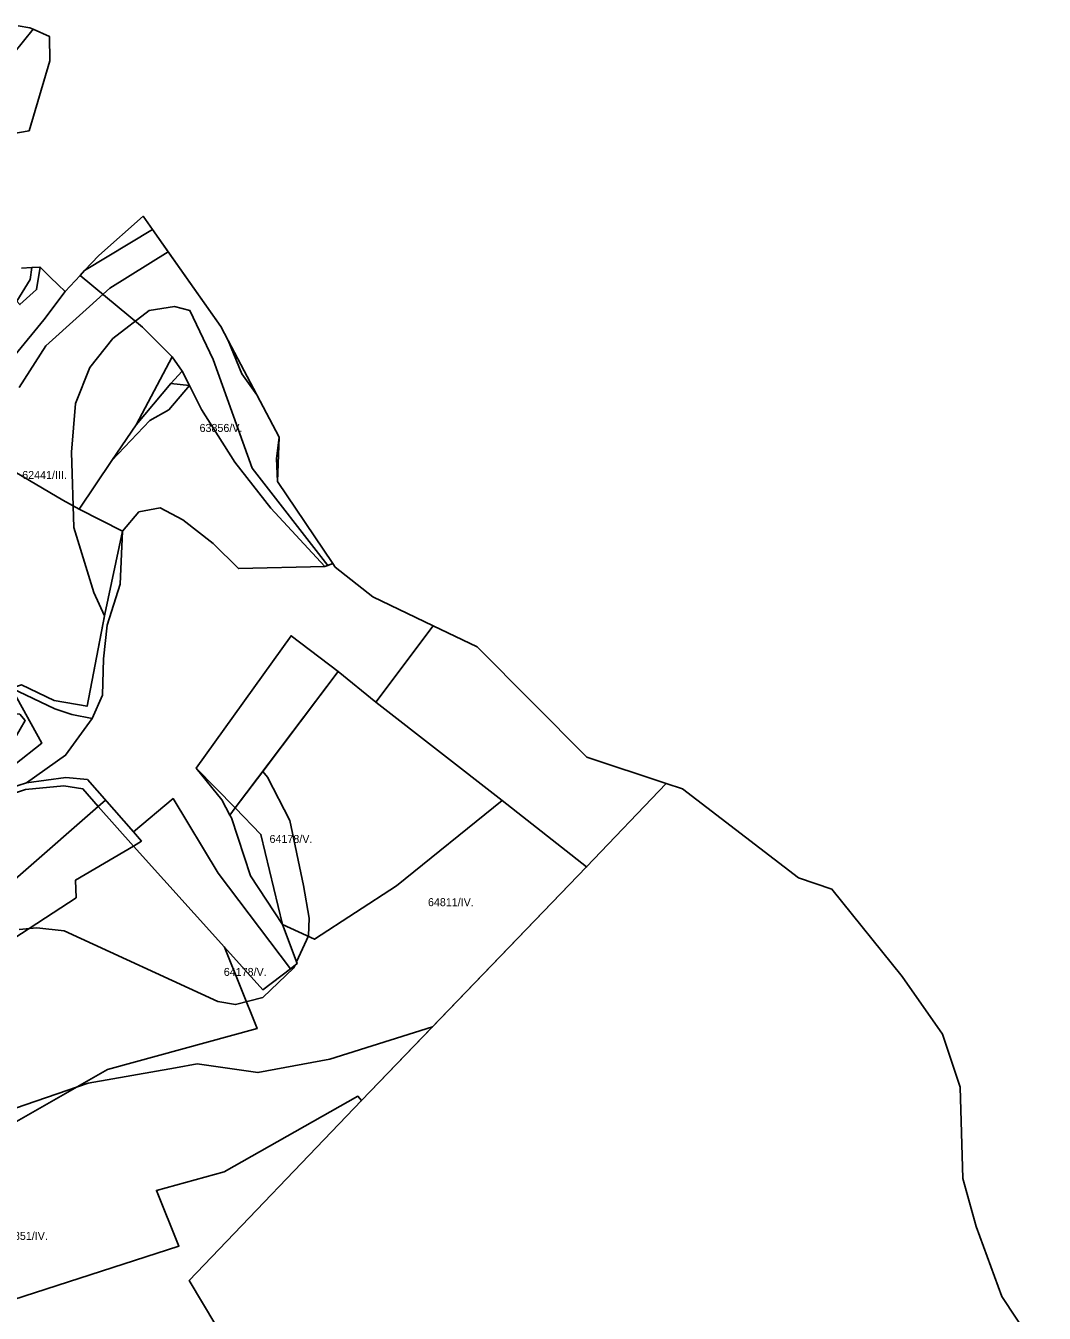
# Model space of a CAD drawing. Extents: x -521261 to -517465, y -1182764 to -1179456.
# Drawn here: x -518235 to -517599, y -1182247 to -1181443 of the extents above; entities that cross this region are included whole.
import ezdxf

# ---------------------------------------------------------------- set-up
doc = ezdxf.new("R2010")
doc.units = 0
for name, color, linetype in [('95560013', 7, 'Continuous'), ('95610013', 7, 'Continuous'), ('95620013', 7, 'Continuous'), ('95630013', 7, 'Continuous'), ('95640013', 7, 'Continuous'), ('95660013', 7, 'Continuous')]:
    doc.layers.add(name, color=color, linetype=linetype)

msp = doc.modelspace()

# ---------------------------------------------------------------- linework, layer by layer
at = {"layer": '95560013'}
for points in [[(-518039.97, -1181846.02), (-518016.25, -1181865.06), (-517937.47, -1181926.51), (-518003.38, -1181979.84), (-518054.75, -1182013.18), (-518074.66, -1182003.92), (-518088.11, -1181947.65), (-518104.15, -1181931.16)], [(-517937.47, -1181926.51), (-517884.7, -1181968.01), (-518025.29, -1182113.9), (-518027.56, -1182111.28), (-518111.08, -1182158.35), (-518153.43, -1182170.1), (-518139.38, -1182204.87), (-518263.83, -1182245.02), (-518424.06, -1182333.99), (-518433.13, -1182315.06), (-518318.58, -1182239.54), (-518350.96, -1182190.35), (-518347.31, -1182180.7), (-518335.12, -1182204.11), (-518240.87, -1182127.03), (-518183.99, -1182094.63), (-518090.51, -1182068.93), (-518110.82, -1182018.11), (-518086.87, -1182044.67), (-518069.54, -1182031.68), (-518065.44, -1182028.22), (-518074.66, -1182003.92), (-518054.75, -1182013.18), (-518003.38, -1181979.84)], [(-518107.48, -1181935.62), (-518104.15, -1181931.16), (-518088.11, -1181947.65), (-518074.66, -1182003.92), (-518094.59, -1181973.57), (-518106.56, -1181937.37)], [(-518167.73, -1181955), (-518110.82, -1182018.11), (-518090.51, -1182068.93), (-518183.99, -1182094.63), (-518240.87, -1182127.03), (-518335.12, -1182204.11), (-518347.31, -1182180.7), (-518342.86, -1182166.04), (-518356.01, -1182102.22), (-518326.89, -1182075.42), (-518296.03, -1182047.39), (-518203.6, -1181987.3), (-518203.86, -1181976.19)]]:
    msp.add_lwpolyline(points, close=True, dxfattribs=at)
at = {"layer": '95610013'}
for points in [[(-518230.37, -1181444.73), (-518220.1, -1181449.28), (-518219.98, -1181464.38), (-518232.93, -1181508.15), (-518243.76, -1181510.04), (-518252.51, -1181510.92), (-518261.84, -1181503.31), (-518242.44, -1181459.71)], [(-518198.24, -1181595.51), (-518155.8, -1181569.88), (-518113.09, -1181630.49), (-518108.52, -1181639.23), (-518100.06, -1181660.08), (-518090.66, -1181673.2), (-518076.8, -1181699.59), (-518078.28, -1181712.88), (-518077.8, -1181727.26), (-518043.21, -1181778.53), (-518048.19, -1181780.36), (-518081.84, -1181743.97), (-518104.4, -1181715.24), (-518125.2, -1181682.29), (-518132.78, -1181667.2), (-518137.2, -1181658.38), (-518143.65, -1181649.33), (-518162.04, -1181630.84), (-518201.08, -1181598.66)], [(-518231.23, -1181593.65), (-518226.03, -1181593.35), (-518228.23, -1181607.32), (-518238.63, -1181616.76), (-518240.53, -1181614.63), (-518232.17, -1181601.16)], [(-518210.43, -1181608.65), (-518201.08, -1181598.66), (-518162.04, -1181630.84), (-518143.65, -1181649.33), (-518166.09, -1181691.8), (-518181.28, -1181714.22), (-518201.57, -1181744.52), (-518211.74, -1181738.87), (-518271.03, -1181704.12), (-518268.81, -1181694.86), (-518257.78, -1181667.72), (-518223.62, -1181626.24)], [(-518108.52, -1181639.23), (-518090.66, -1181673.2), (-518100.06, -1181660.08)], [(-518143.65, -1181649.33), (-518137.2, -1181658.38), (-518144.4, -1181665.99), (-518166.09, -1181691.8)], [(-518137.2, -1181658.38), (-518132.78, -1181667.2), (-518144.4, -1181665.99)], [(-518132.78, -1181667.2), (-518125.2, -1181682.29), (-518104.4, -1181715.24), (-518081.84, -1181743.97), (-518048.19, -1181780.36), (-518102.12, -1181781.59), (-518117.96, -1181765.95), (-518136.81, -1181751.12), (-518151.04, -1181743.73), (-518164.27, -1181746.2), (-518174.5, -1181758.25), (-518201.57, -1181744.52), (-518181.28, -1181714.22), (-518157.59, -1181689.15), (-518145.72, -1181682.4)], [(-518132.78, -1181667.2), (-518145.72, -1181682.4), (-518157.59, -1181689.15), (-518181.28, -1181714.22), (-518166.09, -1181691.8), (-518144.4, -1181665.99)], [(-518273.51, -1181713.67), (-518271.03, -1181704.12), (-518211.74, -1181738.87), (-518201.57, -1181744.52), (-518174.5, -1181758.25), (-518185.6, -1181810.01), (-518196.73, -1181867.61), (-518217.29, -1181863.99), (-518237.7, -1181854.2), (-518243.96, -1181856.31), (-518273.09, -1181840.42), (-518283.47, -1181831.75), (-518289.97, -1181826.31), (-518302.96, -1181825.14), (-518296.94, -1181818.88), (-518287.7, -1181797.29)], [(-518167.72, -1181946.01), (-518142.94, -1181925.35), (-518114.8, -1181971.88), (-518069.54, -1182031.68), (-518086.87, -1182044.67), (-518110.82, -1182018.11), (-518167.73, -1181955), (-518162.77, -1181951.82)]]:
    msp.add_lwpolyline(points, close=True, dxfattribs=at)
at = {"layer": '95620013'}
for points in [[(-518164.27, -1181746.2), (-518151.04, -1181743.73), (-518136.81, -1181751.12), (-518117.96, -1181765.95), (-518102.12, -1181781.59), (-518048.19, -1181780.36), (-518043.21, -1181778.53), (-518041.71, -1181780.74), (-518018.25, -1181799.32), (-517980.44, -1181817.45), (-518016.25, -1181865.06), (-518039.97, -1181846.02), (-518069.24, -1181823.59), (-518128.46, -1181906.25), (-518112.47, -1181926.13), (-518107.48, -1181935.62), (-518106.56, -1181937.37), (-518094.59, -1181973.57), (-518074.66, -1182003.92), (-518065.44, -1182028.22), (-518069.54, -1182031.68), (-518114.8, -1181971.88), (-518142.94, -1181925.35), (-518167.72, -1181946.01), (-518196.51, -1181913.47), (-518210.04, -1181912.15), (-518234.59, -1181915.51), (-518210.07, -1181898.25), (-518193.46, -1181875.24), (-518187.07, -1181860.77), (-518186.5, -1181837.96), (-518184.18, -1181816.88), (-518176.04, -1181791.27), (-518174.5, -1181758.25)], [(-518174.5, -1181758.25), (-518176.04, -1181791.27), (-518184.18, -1181816.88), (-518186.5, -1181837.96), (-518187.07, -1181860.77), (-518193.46, -1181875.24), (-518206.25, -1181872.88), (-518216.74, -1181869.34), (-518243.96, -1181856.31), (-518237.7, -1181854.2), (-518217.29, -1181863.99), (-518196.73, -1181867.61), (-518185.6, -1181810.01)], [(-517980.44, -1181817.45), (-517953.14, -1181830.53), (-517884.53, -1181899.44), (-517834.98, -1181915.87), (-517884.7, -1181968.01), (-517937.47, -1181926.51), (-518016.25, -1181865.06)], [(-518069.24, -1181823.59), (-518039.97, -1181846.02), (-518104.15, -1181931.16), (-518128.46, -1181906.25)], [(-518243.96, -1181856.31), (-518216.74, -1181869.34), (-518206.25, -1181872.88), (-518193.46, -1181875.24), (-518210.07, -1181898.25), (-518234.59, -1181915.51), (-518260.74, -1181923.8), (-518297.47, -1181944.62), (-518324.52, -1181960.18), (-518292.42, -1181936.84), (-518241.77, -1181903.92), (-518224.92, -1181890.6)], [(-518238.76, -1181872.67), (-518248.46, -1181871.63), (-518262.89, -1181874.89), (-518293.39, -1181886.48), (-518243.96, -1181856.31), (-518224.92, -1181890.6), (-518241.77, -1181903.92), (-518292.42, -1181936.84), (-518241.66, -1181887.31), (-518235.39, -1181876.59)], [(-518112.47, -1181926.13), (-518128.46, -1181906.25), (-518104.15, -1181931.16), (-518107.48, -1181935.62)], [(-518025.29, -1182113.9), (-518132.88, -1182226.29), (-518107.95, -1182268.17), (-518147.76, -1182311.32), (-518306.45, -1182392.72), (-518408.71, -1182440.57), (-518421.69, -1182398.59), (-518461.02, -1182411.93), (-518525.73, -1182463.17), (-518552.56, -1182359.4), (-518559.26, -1182337.41), (-518435.2, -1182310.64), (-518433.13, -1182315.06), (-518424.06, -1182333.99), (-518263.83, -1182245.02), (-518139.38, -1182204.87), (-518153.43, -1182170.1), (-518111.08, -1182158.35), (-518027.56, -1182111.28)]]:
    msp.add_lwpolyline(points, close=True, dxfattribs=at)
for points in [[(-518107.95, -1182268.17), (-518132.88, -1182226.29), (-518025.29, -1182113.9), (-517884.7, -1181968.01), (-517834.98, -1181915.87), (-517824.86, -1181919.18), (-517752.33, -1181974.82), (-517731.51, -1181981.82), (-517687.7, -1182036.43), (-517662.52, -1182072.49), (-517651.3, -1182105.53), (-517649.72, -1182162.65), (-517641.34, -1182192.65), (-517625.29, -1182236.25), (-517598.88, -1182276.27)], [(-518235.18, -1181919.56), (-518211.21, -1181917.3), (-518199.33, -1181919.3), (-518189.71, -1181930.34), (-518332.06, -1182054.74)]]:
    msp.add_lwpolyline(points, dxfattribs=at)
at = {"layer": '95630013'}
msp.add_lwpolyline([(-518237.69, -1181594.04), (-518231.23, -1181593.65), (-518232.17, -1181601.16), (-518240.53, -1181614.63)], dxfattribs=at)
at = {"layer": '95640013'}
for points in [[(-518239.78, -1181442.56), (-518232.48, -1181443.8), (-518230.37, -1181444.73), (-518242.44, -1181459.71)], [(-518238.63, -1181616.76), (-518228.23, -1181607.32), (-518226.03, -1181593.35), (-518221.11, -1181598.17), (-518219.69, -1181599.57), (-518214.7, -1181604.46), (-518210.43, -1181608.65), (-518223.62, -1181626.24), (-518257.78, -1181667.72)]]:
    msp.add_lwpolyline(points, dxfattribs=at)
for points in [[(-518161.68, -1181561.54), (-518155.8, -1181569.88), (-518198.24, -1181595.51), (-518189.41, -1181586)], [(-518076.8, -1181699.59), (-518077.8, -1181727.26), (-518078.28, -1181712.88)], [(-518210.04, -1181912.15), (-518196.51, -1181913.47), (-518167.72, -1181946.01), (-518162.77, -1181951.82), (-518167.73, -1181955), (-518189.71, -1181930.34), (-518199.33, -1181919.3), (-518211.21, -1181917.3), (-518235.18, -1181919.56), (-518260.36, -1181927.92), (-518293.89, -1181947.03), (-518355.83, -1182017.34), (-518386.67, -1182049.7), (-518391.97, -1182046.38), (-518387.41, -1182044.05), (-518365.6, -1182022.45), (-518359.15, -1182015.32), (-518331.24, -1181984.11), (-518297.47, -1181944.62), (-518260.74, -1181923.8), (-518234.59, -1181915.51)], [(-518167.73, -1181955), (-518203.86, -1181976.19), (-518203.6, -1181987.3), (-518296.03, -1182047.39), (-518326.89, -1182075.42), (-518325.37, -1182067.68), (-518332.06, -1182054.74), (-518189.71, -1181930.34)]]:
    msp.add_lwpolyline(points, close=True, dxfattribs=at)
at = {"layer": '95660013'}
for points in [[(-518239.78, -1181442.56), (-518232.48, -1181443.8), (-518230.37, -1181444.73), (-518220.1, -1181449.28), (-518219.98, -1181464.38), (-518232.93, -1181508.15), (-518243.76, -1181510.04)], [(-518237.69, -1181594.04), (-518231.23, -1181593.65), (-518226.03, -1181593.35), (-518221.11, -1181598.17), (-518219.69, -1181599.57), (-518214.7, -1181604.46), (-518210.43, -1181608.65), (-518201.08, -1181598.66), (-518198.24, -1181595.51), (-518189.41, -1181586), (-518161.68, -1181561.54), (-518155.8, -1181569.88), (-518146.03, -1181583.74), (-518182.5, -1181606.5), (-518222.5, -1181642.5), (-518239, -1181668.5)], [(-518239, -1181668.5), (-518222.5, -1181642.5), (-518182.5, -1181606.5), (-518146.03, -1181583.74), (-518113.09, -1181630.49), (-518108.52, -1181639.23), (-518090.66, -1181673.2), (-518076.8, -1181699.59), (-518077.8, -1181727.26), (-518043.21, -1181778.53), (-518046.36, -1181779.69), (-518093.5, -1181719), (-518118, -1181651), (-518132.5, -1181620.5), (-518142, -1181618), (-518158, -1181620.5), (-518180.5, -1181638), (-518195, -1181656), (-518204, -1181678.5), (-518206.5, -1181709), (-518205, -1181756), (-518192.5, -1181796.5), (-518185.82, -1181811.14), (-518196.73, -1181867.61), (-518217.29, -1181863.99), (-518237.7, -1181854.2)], [(-518237.7, -1181854.2), (-518217.29, -1181863.99), (-518196.73, -1181867.61), (-518185.82, -1181811.14), (-518185.6, -1181810.01), (-518174.5, -1181758.25), (-518164.27, -1181746.2), (-518151.04, -1181743.73), (-518136.81, -1181751.12), (-518117.96, -1181765.95), (-518102.12, -1181781.59), (-518048.19, -1181780.36), (-518046.36, -1181779.69), (-518043.21, -1181778.53), (-518041.71, -1181780.74), (-518018.25, -1181799.32), (-517980.44, -1181817.45), (-517953.14, -1181830.53), (-517884.53, -1181899.44), (-517834.98, -1181915.87), (-517824.86, -1181919.18), (-517752.33, -1181974.82), (-517731.51, -1181981.82), (-517687.7, -1182036.43), (-517662.52, -1182072.49), (-517651.3, -1182105.53), (-517649.72, -1182162.65), (-517641.34, -1182192.65), (-517625.29, -1182236.25), (-517598.88, -1182276.27)], [(-518263.83, -1182245.02), (-518139.38, -1182204.87), (-518153.43, -1182170.1), (-518111.08, -1182158.35), (-518027.56, -1182111.28), (-518025.29, -1182113.9), (-517981.02, -1182067.96), (-517884.7, -1181968.01), (-517937.47, -1181926.51), (-518016.25, -1181865.06), (-518039.97, -1181846.02), (-518087.02, -1181908.43), (-518104.15, -1181931.16), (-518107.48, -1181935.62), (-518106.56, -1181937.37), (-518094.59, -1181973.57), (-518074.66, -1182003.92), (-518065.81, -1182027.25), (-518065.44, -1182028.22), (-518066.74, -1182029.32), (-518069.54, -1182031.68), (-518114.8, -1181971.88), (-518142.94, -1181925.35), (-518167.72, -1181946.01), (-518185.24, -1181926.21), (-518189.71, -1181930.34), (-518332.06, -1182054.74)], [(-518239, -1182007), (-518228, -1182006), (-518211, -1182008), (-518115, -1182052), (-518104, -1182054), (-518087, -1182049.5), (-518067.5, -1182031), (-518066.74, -1182029.32), (-518065.44, -1182028.22), (-518065.81, -1182027.25), (-518058.5, -1182011), (-518058, -1182000), (-518061.5, -1181979.5), (-518070, -1181939), (-518084, -1181912), (-518087.02, -1181908.43), (-518039.97, -1181846.02), (-518016.25, -1181865.06), (-517937.47, -1181926.51), (-517884.7, -1181968.01), (-517981.02, -1182067.96), (-518045, -1182088), (-518090, -1182096.5), (-518128, -1182091), (-518141.5, -1182093.5), (-518196, -1182103), (-518248, -1182121)], [(-518332.06, -1182054.74), (-518189.71, -1181930.34), (-518185.24, -1181926.21), (-518167.72, -1181946.01), (-518142.94, -1181925.35), (-518114.8, -1181971.88), (-518069.54, -1182031.68), (-518066.74, -1182029.32), (-518067.5, -1182031), (-518087, -1182049.5), (-518104, -1182054), (-518115, -1182052), (-518211, -1182008), (-518228, -1182006), (-518239, -1182007)], [(-518248, -1182121), (-518196, -1182103), (-518141.5, -1182093.5), (-518128, -1182091), (-518090, -1182096.5), (-518045, -1182088), (-517981.02, -1182067.96), (-518025.29, -1182113.9), (-518027.56, -1182111.28), (-518111.08, -1182158.35), (-518153.43, -1182170.1), (-518139.38, -1182204.87), (-518263.83, -1182245.02)]]:
    msp.add_lwpolyline(points, dxfattribs=at)
for points in [[(-518093.5, -1181719), (-518046.36, -1181779.69), (-518048.19, -1181780.36), (-518102.12, -1181781.59), (-518117.96, -1181765.95), (-518136.81, -1181751.12), (-518151.04, -1181743.73), (-518164.27, -1181746.2), (-518174.5, -1181758.25), (-518185.6, -1181810.01), (-518185.82, -1181811.14), (-518192.5, -1181796.5), (-518205, -1181756), (-518206.5, -1181709), (-518204, -1181678.5), (-518195, -1181656), (-518180.5, -1181638), (-518158, -1181620.5), (-518142, -1181618), (-518132.5, -1181620.5), (-518118, -1181651)], [(-518058.5, -1182011), (-518065.81, -1182027.25), (-518074.66, -1182003.92), (-518094.59, -1181973.57), (-518106.56, -1181937.37), (-518107.48, -1181935.62), (-518104.15, -1181931.16), (-518087.02, -1181908.43), (-518084, -1181912), (-518070, -1181939), (-518061.5, -1181979.5), (-518058, -1182000)]]:
    msp.add_lwpolyline(points, close=True, dxfattribs=at)

# ---------------------------------------------------------------- texts
for s, rotation, p in [('63856/V.', 360, (-518126.43, -1181696.28)), ('62441/III.', 360, (-518237.2, -1181725.68)), ('64178/V.', 360, (-518082.74, -1181953.02)), ('64811/IV.', 360, (-517983.79, -1181992.51)), ('64178/V.', 360, (-518111.29, -1182036.08)), ('64851/IV.', 0, (-518249.82, -1182200.97))]:
    msp.add_text(s, height=5, rotation=rotation, dxfattribs=at).set_placement(p)

doc.saveas('drawing.dxf')
